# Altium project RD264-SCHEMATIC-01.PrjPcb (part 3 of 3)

## Sheet 6.SchDoc
size 420 x 297 mm
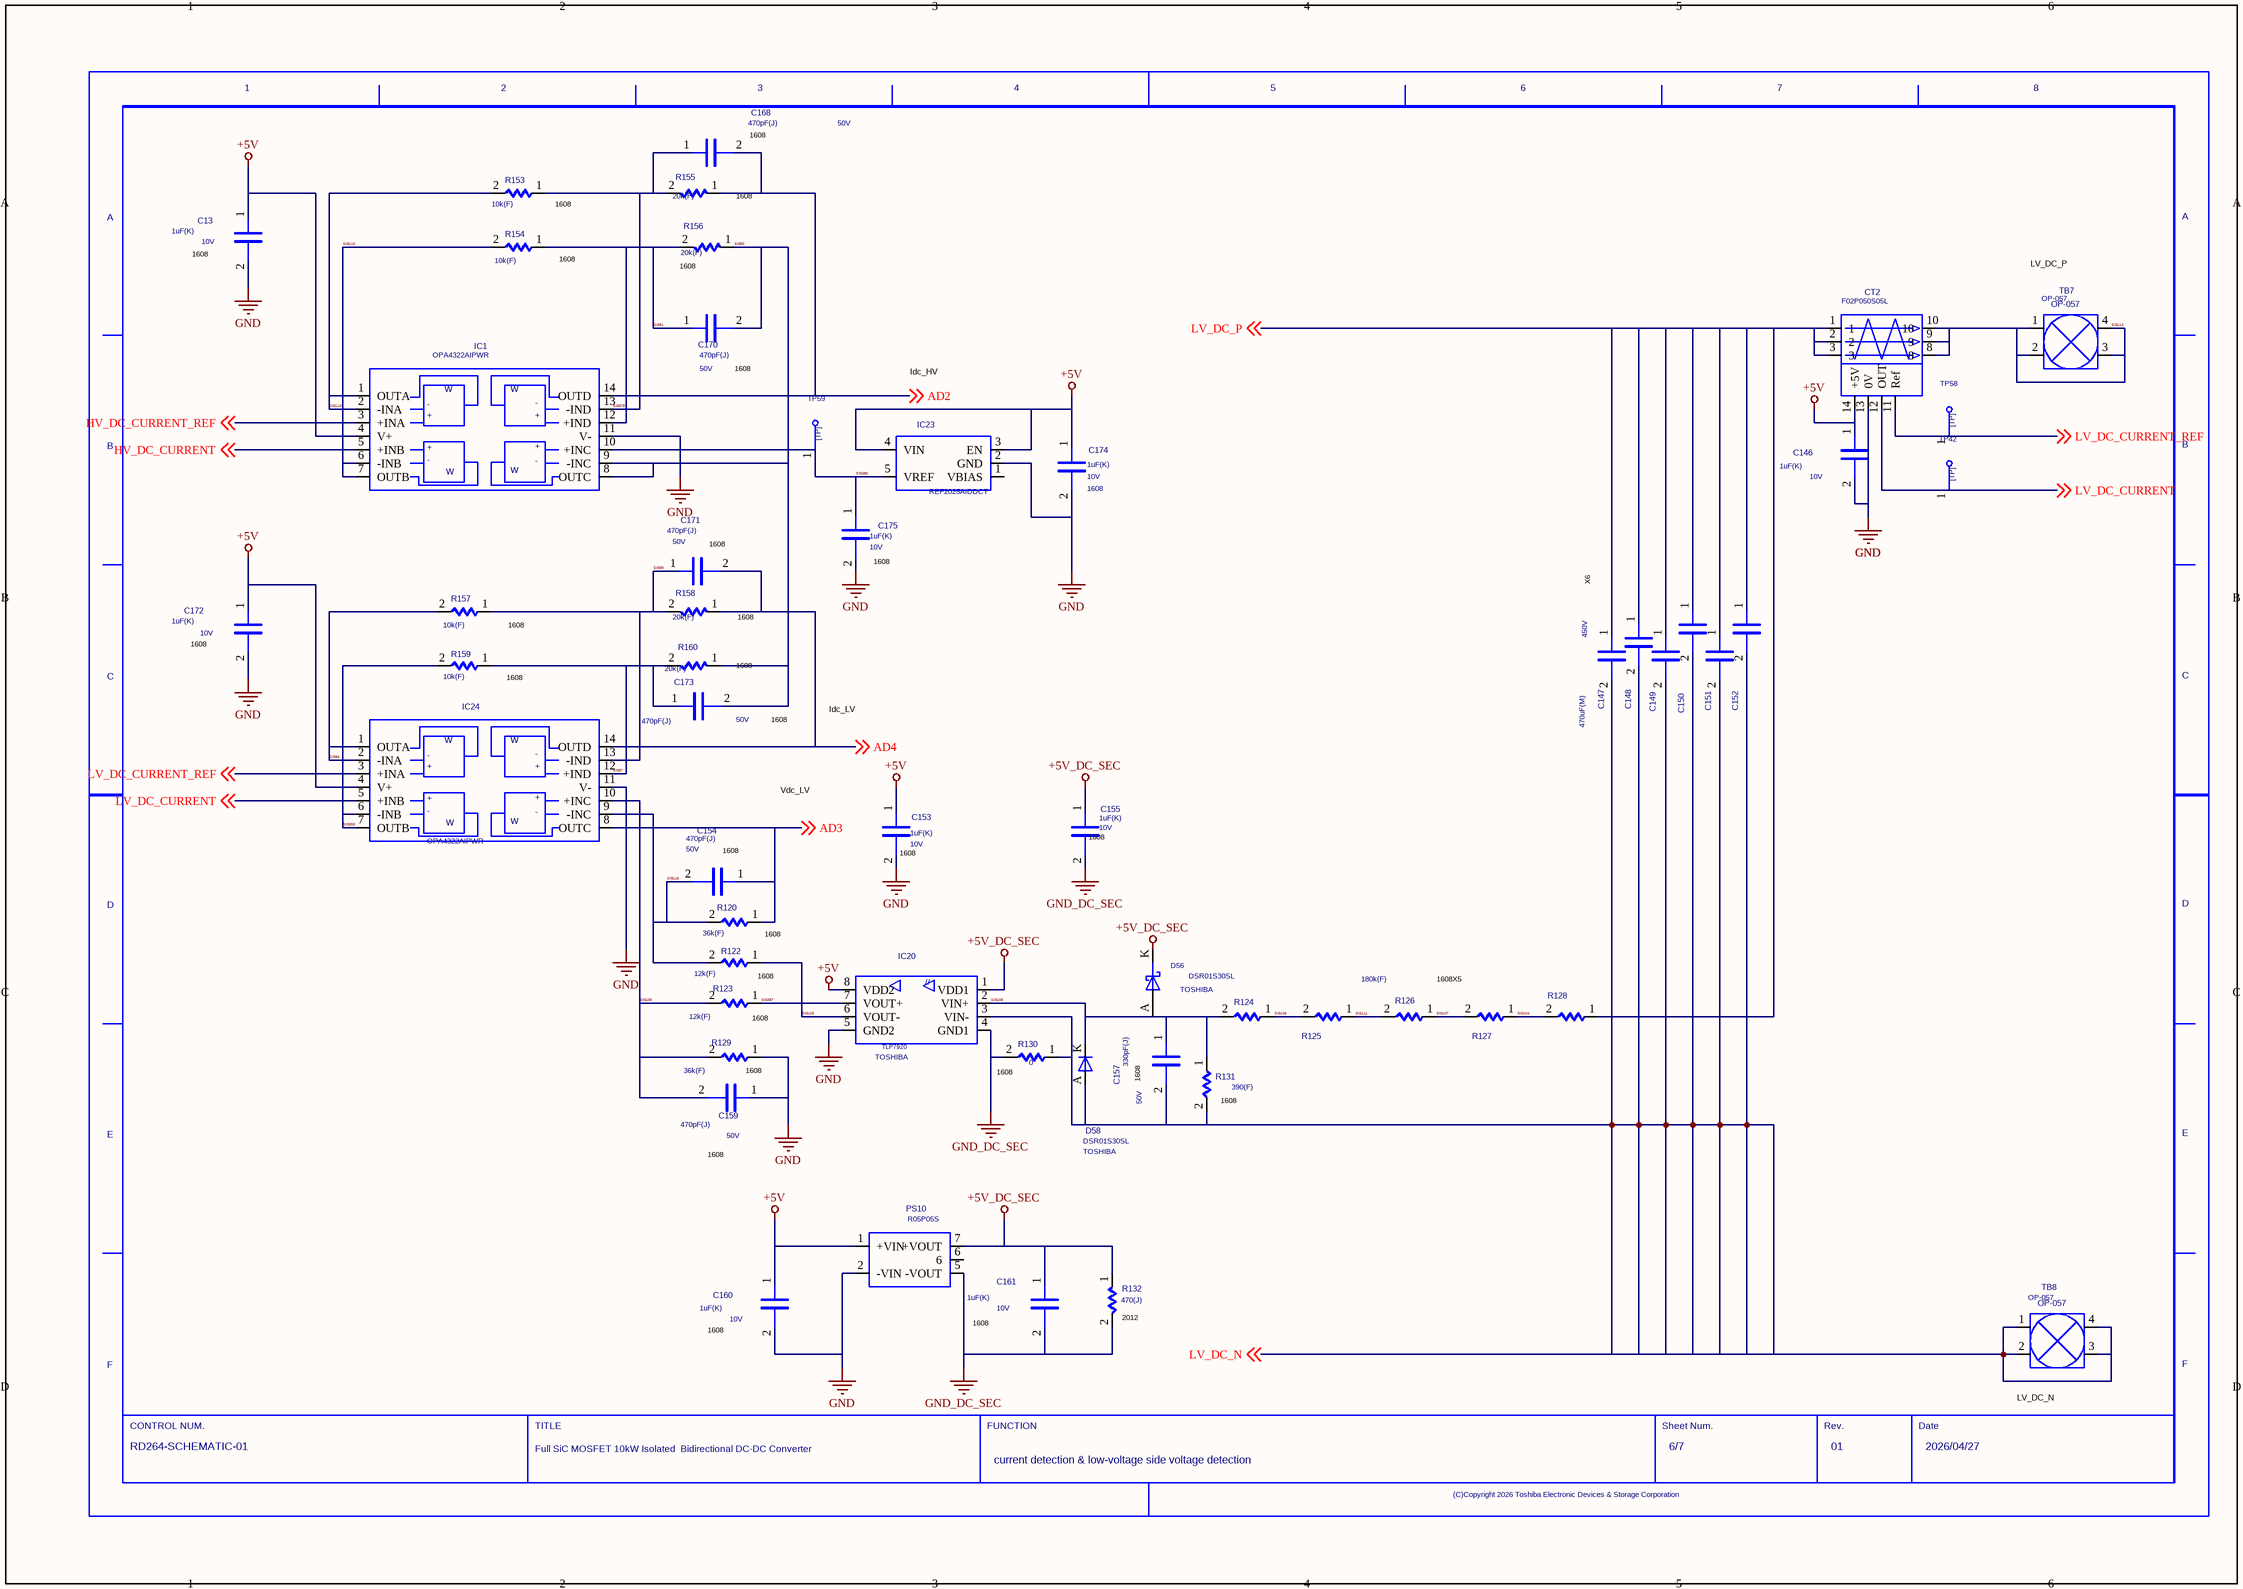
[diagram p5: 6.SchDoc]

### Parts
(Parts that share a designator on the sheet are numbered #1, #2 ... from top to bottom, then left to right.)
C13  VAL1: 1uF(K)  VAL2: 10V  (hidden comment: GRM188R71A105KA61D)
C146  VAL1: 1uF(K)  VAL2: 10V  (hidden comment: GRM188R71A105KA61D)
C147  VAL1: 470uF(M)  VAL2: 450V  (hidden comment: ESMR451VSN471MR40S)
C148  ESMR451VSN471MR40S  (value not drawn)
C149  ESMR451VSN471MR40S  (value not drawn)
C150  ESMR451VSN471MR40S  (value not drawn)
C151  ESMR451VSN471MR40S  (value not drawn)
C152  ESMR451VSN471MR40S  (value not drawn)
C153  VAL2: 10V  VAL1: 1uF(K)  (hidden comment: GRM188R71A105KA61D)
C154  VAL1: 470pF(J)  VAL2: 50V  (hidden comment: GRM1885C1H471JA01D)
C155  VAL1: 1uF(K)  VAL2: 10V  (hidden comment: GRM188R71A105KA61D)
C157  VAL1: 330pF(J)  VAL2: 50V  (hidden comment: GRM1885C1H331JA01D)
C159  VAL1: 470pF(J)  VAL2: 50V  (hidden comment: GRM1885C1H471JA01D)
C160  VAL1: 1uF(K)  VAL2: 10V  (hidden comment: GRM188R71A105KA61D)
C161  VAL1: 1uF(K)  VAL2: 10V  (hidden comment: GRM188R71A105KA61D)
C168  VAL1: 470pF(J)  VAL2: 50V  (hidden comment: GRM1885C1H471JA01D)
C170  VAL1: 470pF(J)  VAL2: 50V  (hidden comment: GRM1885C1H471JA01D)
C171  VAL1: 470pF(J)  VAL2: 50V  (hidden comment: GRM1885C1H471JA01D)
C172  VAL2: 10V  VAL1: 1uF(K)  (hidden comment: GRM188R71A105KA61D)
C173  VAL1: 470pF(J)  VAL2: 50V  (hidden comment: GRM1885C1H471JA01D)
C174  VAL1: 1uF(K)  VAL2: 10V  SIZECODESMD: 1608  (hidden comment: GRM188R71A105KA61D)
C175  VAL1: 1uF(K)  VAL2: 10V  (hidden comment: GRM188R71A105KA61D)
CT2  F02P050S05L
D56  VAL3: DSR01S30SL  USERCOMPTEXT3: TOSHIBA  (hidden comment: SBD)
D58  USERCOMPTEXT3: TOSHIBA  (hidden comment: DSR01S30SL)
IC1  OPA4322AIPWR
IC20  VAL3: TLP7920  USERCOMPTEXT3: TOSHIBA  (hidden comment: TLP7920(LF5,TP5))
IC23  REF2025AIDDCT
IC24  OPA4322AIPWR
PS10  R05P05S
R120  VAL1: 36k(F)  (hidden comment: RK73G1JTTD3602F)
R122  VAL1: 12k(F)  (hidden comment: RK73G1JTTD1202F)
R123  VAL1: 12k(F)  (hidden comment: RK73G1JTTD1202F)
R124  ERJ3EKF1803V  (value not drawn)
R125  ERJ3EKF1803V  (value not drawn)
R126  VAL1: 180k(F)  (hidden comment: ERJ3EKF1803V)
R127  ERJ3EKF1803V  (value not drawn)
R128  ERJ3EKF1803V  (value not drawn)
R129  VAL1: 36k(F)  (hidden comment: RK73G1JTTD3602F)
R130  VAL1: 0  (hidden comment: RK73Z1JTTD)
R131  VAL1: 390(F)  (hidden comment: RK73G1JTTD3900F)
R132  VAL1: 470(J)  (hidden comment: RK73B2ATTD471J)
R153  VAL1: 10k(F)  (hidden comment: RK73H1JTTD1002F)
R154  VAL1: 10k(F)  (hidden comment: RK73H1JTTD1002F)
R155  VAL1: 20k(F)  (hidden comment: RK73H1JTTD2002F)
R156  VAL1: 20k(F)  (hidden comment: RK73H1JTTD2002F)
R157  VAL1: 10k(F)  (hidden comment: RK73H1JTTD1002F)
R158  VAL1: 20k(F)  (hidden comment: RK73H1JTTD2002F)
R159  VAL1: 10k(F)  (hidden comment: RK73H1JTTD1002F)
R160  VAL1: 20k(F)  (hidden comment: RK73H1JTTD2002F)
TB7  OP-057
TB8  OP-057
TP42  TP  (value not drawn)
TP58  TP  (value not drawn)
TP59  TP  (value not drawn)
U?#6  DATE: 2026/04/27  DRAWINGNUMBER: RD264-SCHEMATIC-01  TITLE: Full SiC MOSFET 10kW Isolated / Bidirectional DC-DC Converter  FUNCTION: current detection / & low-voltage side voltage detection  SHEETNUMBER: 6/7  REVISION: 01  (hidden comment: WAKU_DEF100)

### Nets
+5V: C13.1 C146.1 C153.1 C160.1 C172.1 C174.1 CT2.14(+5V) IC1.4(V+) IC20.8(VDD2) IC23.3(EN) IC23.4(VIN) IC24.4(V+) PS10.1(+VIN)
+5V_DC_SEC: C155.1 C161.1 D56.K(C) IC20.1(VDD1) PS10.7(+VOUT) R132.1
GND: C13.2 C146.2 C153.2 C159.1 C160.2 C172.2 C174.2 C175.2 CT2.13(0V) IC1.11(V-) IC20.5(GND2) IC23.2(GND) IC24.11(V-) PS10.2(-VIN) R129.1
GND_DC_SEC: C155.2 C161.2 IC20.4(GND1) PS10.5(-VOUT) R130.2 R132.2
AD2: C168.2 IC1.14(OUTD) R155.1 ; off-sheet AD2
AD3: C154.1 IC24.8(OUTC) R120.1 ; off-sheet AD3
AD4: C171.2 IC24.14(OUTD) R158.1 ; off-sheet AD4
HV_DC_CURRENT: IC1.5(+INB) ; off-sheet HV_DC_CURRENT
HV_DC_CURRENT_REF: IC1.3(+INA) ; off-sheet HV_DC_CURRENT_REF
LV_DC_CURRENT: CT2.12(OUT) IC24.5(+INB) TP42.1 ; off-sheet LV_DC_CURRENT
LV_DC_CURRENT_REF: CT2.11(Ref) IC24.3(+INA) TP58.1 ; off-sheet LV_DC_CURRENT_REF
LV_DC_N: C147.2 C148.2 C149.2 C150.2 C151.2 C152.2 C157.2 D58.A IC20.3(VIN-) R130.1 R131.2 TB8.1 TB8.2 TB8.3 TB8.4 ; off-sheet LV_DC_N
LV_DC_P: C147.1 C148.1 C149.1 C150.1 C151.1 C152.1 CT2.1 CT2.2 CT2.3 R128.1 ; off-sheet LV_DC_P
SIG91: C170.1 IC1.12(+IND) R154.1 R156.2
SIG92: C170.2 C173.2 IC1.8(OUTC) IC1.9(-INC) R156.1 R160.1
SIG94: IC24.1(OUTA) IC24.2(-INA) R157.2
SIG97: C173.1 IC24.12(+IND) R159.1 R160.2
SIG99: C171.1 IC24.13(-IND) R157.1 R158.2
SIG103: IC20.6(VOUT-) R122.1
SIG104: R127.1 R128.2
SIG105: R124.1 R125.2
SIG106: C159.2 IC24.10(+INC) R123.2 R129.2
SIG107: R126.1 R127.2
SIG108: C157.1 D56.A D58.K(C) IC20.2(VIN+) R124.2 R131.1
SIG110: IC1.1(OUTA) IC1.2(-INA) R153.2
SIG111: R125.1 R126.2
SIG113: IC1.6(-INB) IC1.7(OUTB) R154.2
SIG114: CT2.8 CT2.9 CT2.10 TB7.1 TB7.2 TB7.3 TB7.4
SIG115: C154.2 IC24.9(-INC) R120.2 R122.2
SIG378: C168.1 IC1.13(-IND) R153.1 R155.2
SIG380: C175.1 IC1.10(+INC) IC23.5(VREF) TP59.1
SIG387: IC20.7(VOUT+) R123.1
SIG393: IC24.6(-INB) IC24.7(OUTB) R159.2

Not connected (* = marked no-connect by the designer): IC23 1(VBIAS); PS10 6

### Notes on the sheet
- (near C168) 1608
- (near C13) 1608
- (near R153) 1608
- (near R154) 1608
- 1608
- (near R156) 1608
- LV_DC_P
- (near C170) 1608
- Idc_HV
- (near C171) 1608
- (near C175) 1608
- X6
- (near C172) 1608
- (near R159) 1608
- (near C173) 1608
- Idc_LV
- Vdc_LV
- (near C154) 1608
- (near C153) 1608
- (near C155) 1608
- 1608X5
- (near R129) 1608
- (near R123) 1608
- (near R130) 1608
- (near C157) 1608
- (near R131) 1608
- (near C160) 1608
- (near R132) 2012
- (near TB8) LV_DC_N

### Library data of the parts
C13 = C_Dup1: ORIGINALSYMBOLORIGIN: (0,4826); COMP: C-GRM188R71A105KA61D; TIME: 14:31:23; UPDATEUSER: t5459927; SAVECOUNT: 1; INSTANCENAME: INS17335180; REFERENCE TEMPLATE: C; COMPONENTNAME: C_C.Normal_package; NOTE: 1uF 10V
C146 = C_Dup1: ORIGINALSYMBOLORIGIN: (0,4826); COMP: C-GRM188R71A105KA61D; TIME: 14:31:23; UPDATEUSER: t5459927; SAVECOUNT: 1; INSTANCENAME: INS17154372; REFERENCE TEMPLATE: C; COMPONENTNAME: C_C.Normal_package; NOTE: 1uF 10V
C147 = C_Dup1: ORIGINALSYMBOLORIGIN: (0,4826); COMP: C-ESMR451VSN471MR40S; TIME: 14:31:23; UPDATEUSER: t5459927; SAVECOUNT: 1; INSTANCENAME: INS17110408; REFERENCE TEMPLATE: C; COMPONENTNAME: C_C.Normal_package; NOTE: 470uF 450V
C148 = C_Dup1: ORIGINALSYMBOLORIGIN: (0,4826); COMP: C-ESMR451VSN471MR40S; TIME: 14:31:23; UPDATEUSER: t5459927; SAVECOUNT: 1; INSTANCENAME: INS17110416; REFERENCE TEMPLATE: C; COMPONENTNAME: C_C.Normal_package; NOTE: 470uF 450V; VAL1: 470uF(M); VAL2: 450V
C149 = C_Dup1: ORIGINALSYMBOLORIGIN: (0,4826); COMP: C-ESMR451VSN471MR40S; TIME: 14:31:23; UPDATEUSER: t5459927; SAVECOUNT: 1; INSTANCENAME: INS17110424; REFERENCE TEMPLATE: C; COMPONENTNAME: C_C.Normal_package; NOTE: 470uF 450V; VAL1: 470uF(M); VAL2: 450V
C150 = C_Dup1: ORIGINALSYMBOLORIGIN: (0,4826); COMP: C-ESMR451VSN471MR40S; TIME: 14:31:23; UPDATEUSER: t5459927; SAVECOUNT: 1; INSTANCENAME: INS17110469; REFERENCE TEMPLATE: C; COMPONENTNAME: C_C.Normal_package; NOTE: 470uF 450V; VAL1: 470uF(M); VAL2: 450V
C151 = C_Dup1: ORIGINALSYMBOLORIGIN: (0,4826); COMP: C-ESMR451VSN471MR40S; TIME: 14:31:23; UPDATEUSER: t5459927; SAVECOUNT: 1; INSTANCENAME: INS17110477; REFERENCE TEMPLATE: C; COMPONENTNAME: C_C.Normal_package; NOTE: 470uF 450V; VAL1: 470uF(M); VAL2: 450V
C152 = C_Dup1: ORIGINALSYMBOLORIGIN: (0,4826); COMP: C-ESMR451VSN471MR40S; TIME: 14:31:23; UPDATEUSER: t5459927; SAVECOUNT: 1; INSTANCENAME: INS17110485; REFERENCE TEMPLATE: C; COMPONENTNAME: C_C.Normal_package; NOTE: 470uF 450V; VAL1: 470uF(M); VAL2: 450V
C153 = C_Dup1: ORIGINALSYMBOLORIGIN: (0,4826); COMP: C-GRM188R71A105KA61D; TIME: 14:31:23; UPDATEUSER: t5459927; SAVECOUNT: 1; NOTE: 1uF 10V; FUNCN: C_C.Normal_package; REFERENCE TEMPLATE: C; INSTANCENAME: INS17110613
C154 = C_Dup1: ORIGINALSYMBOLORIGIN: (0,4826); COMP: C-GRM1885C1H471JA01D; TIME: 14:31:23; UPDATEUSER: t5459927; SAVECOUNT: 1; INSTANCENAME: INS17110583; REFERENCE TEMPLATE: C; COMPONENTNAME: C_C.Normal_package; NOTE: 470pF 50V
C155 = C_Dup1: ORIGINALSYMBOLORIGIN: (0,4826); COMP: C-GRM188R71A105KA61D; TIME: 14:31:23; UPDATEUSER: t5459927; SAVECOUNT: 1; INSTANCENAME: INS17110613; REFERENCE TEMPLATE: C; COMPONENTNAME: C_C.Normal_package; NOTE: 1uF 10V
C157 = C_Dup1: ORIGINALSYMBOLORIGIN: (0,4826); COMP: C-GRM1885C1H331JA01D; TIME: 14:31:23; UPDATEUSER: t5459927; SAVECOUNT: 1; INSTANCENAME: INS17110887; REFERENCE TEMPLATE: C; COMPONENTNAME: C_C.Normal_package; NOTE: 330pF 50V
C159 = C_Dup1: ORIGINALSYMBOLORIGIN: (0,4826); COMP: C-GRM1885C1H471JA01D; TIME: 14:31:23; UPDATEUSER: t5459927; SAVECOUNT: 1; INSTANCENAME: INS17110939; REFERENCE TEMPLATE: C; COMPONENTNAME: C_C.Normal_package; NOTE: 470pF 50V
C160 = C_Dup1: ORIGINALSYMBOLORIGIN: (0,4826); COMP: C-GRM188R71A105KA61D; TIME: 14:31:23; UPDATEUSER: t5459927; SAVECOUNT: 1; INSTANCENAME: INS17111029; REFERENCE TEMPLATE: C; COMPONENTNAME: C_C.Normal_package; NOTE: 1uF 10V
C161 = C_Dup1: ORIGINALSYMBOLORIGIN: (0,4826); COMP: C-GRM188R71A105KA61D; TIME: 14:31:23; UPDATEUSER: t5459927; SAVECOUNT: 1; INSTANCENAME: INS17111037; REFERENCE TEMPLATE: C; COMPONENTNAME: C_C.Normal_package; NOTE: 1uF 10V
C168 = C_Dup1: ORIGINALSYMBOLORIGIN: (0,4826); COMP: C-GRM1885C1H471JA01D; TIME: 14:31:23; UPDATEUSER: t5459927; SAVECOUNT: 1; INSTANCENAME: INS17330257; REFERENCE TEMPLATE: C; COMPONENTNAME: C_C.Normal_package; NOTE: 470pF 50V
C170 = C_Dup1: ORIGINALSYMBOLORIGIN: (0,4826); COMP: C-GRM1885C1H471JA01D; TIME: 14:31:23; UPDATEUSER: t5459927; SAVECOUNT: 1; INSTANCENAME: INS17330365; REFERENCE TEMPLATE: C; COMPONENTNAME: C_C.Normal_package; NOTE: 470pF 50V
C171 = C_Dup1: ORIGINALSYMBOLORIGIN: (0,4826); COMP: C-GRM1885C1H471JA01D; TIME: 14:31:23; UPDATEUSER: t5459927; SAVECOUNT: 1; INSTANCENAME: INS17330483; REFERENCE TEMPLATE: C; COMPONENTNAME: C_C.Normal_package; NOTE: 470pF 50V
C172 = C_Dup1: ORIGINALSYMBOLORIGIN: (0,4826); COMP: C-GRM188R71A105KA61D; TIME: 14:31:23; UPDATEUSER: t5459927; SAVECOUNT: 1; NOTE: 1uF 10V; FUNCN: C_C.Normal_package; REFERENCE TEMPLATE: C; INSTANCENAME: INS17335180
C173 = C_Dup1: ORIGINALSYMBOLORIGIN: (0,4826); COMP: C-GRM1885C1H471JA01D; TIME: 14:31:23; UPDATEUSER: t5459927; SAVECOUNT: 1; INSTANCENAME: INS17330591; REFERENCE TEMPLATE: C; COMPONENTNAME: C_C.Normal_package; NOTE: 470pF 50V
C174 = C_Dup1: ORIGINALSYMBOLORIGIN: (0,4826); COMP: C-GRM188R71A105KA61D; TIME: 14:31:23; UPDATEUSER: t5459927; SAVECOUNT: 1; INSTANCENAME: INS17336633; REFERENCE TEMPLATE: C; COMPONENTNAME: C_C.Normal_package; NOTE: 1uF 10V
C175 = C_Dup1: ORIGINALSYMBOLORIGIN: (0,4826); COMP: C-GRM188R71A105KA61D; TIME: 14:31:23; UPDATEUSER: t5459927; SAVECOUNT: 1; INSTANCENAME: INS17330751; REFERENCE TEMPLATE: C; COMPONENTNAME: C_C.Normal_package; NOTE: 1uF 10V
CT2 = F02P050S05L: Currnt Transducer; COMP: CT-F02P050S05L; MAKER: Tamura; NOTE: 50At; TIME: 14:31:25; UPDATEUSER: t5459927; UPDATETIME: 14:13:05; SAVECOUNT: 3; SAVEAREA0: -15517,-13418,30208,5711; OriginalSymbolOrigin: (0,0)
D56 = SBD: SAVEAREA0: -4630,-153,17114,13055; TIME: 14:49:55; UPDATEUSER: fukuda-y; UPDATETIME: 08:16:22; SAVECOUNT: 9; OriginalSymbolOrigin: (5080,5080)
D58 = D: PART NUMBER: TMP-433; UPDATEUSER: t5459927; COMP: D-DSR01S30SL; UPDATETIME: 14:31:23; SAVECOUNT: 1; SAVEAREA0: -225,-91,12804,7836; ORIGINALSYMBOLORIGIN: (0,0); INSTANCENAME: INS17313401; FUNCN: D_D.Normal_package; NOTE: 30V 0.1A
IC1 IC24 = OPA4322AIPWR: IC OPAMP; COMP: IC-OPA4322AIPWR; MAKER: Texas Instruments; NOTE: Quad; TIME: 14:31:23; UPDATEUSER: t5459927; UPDATETIME: 14:10:26; SAVECOUNT: 3; SAVEAREA0: -4407,-29582,46539,7769; OriginalSymbolOrigin: (0,0)
IC20 = TLP7920_LF5: Isolation Amplifier; COMP: IC-TLP7920_LF5_TP5; TIME: 14:31:23; UPDATEUSER: t5459927; UPDATETIME: 14:29:27; SAVECOUNT: 3; SAVEAREA0: -27477,-19134,50054,13301; OriginalSymbolOrigin: (0,0)
IC23 = REF2025AIDDCT: 2Voltage References; COMP: IC-REF2025AIDDCT; MAKER: Texas Instruments; TIME: 14:31:24; UPDATEUSER: t5459927; UPDATETIME: 14:11:39; SAVECOUNT: 3; SAVEAREA0: -3467,-13658,20665,4033; OriginalSymbolOrigin: (0,0)
PS10 = R05P05S: DCDC Converter; COMP: PS-R05P05S; MAKER: RECOM; NOTE: 5V in 5V out; TIME: 14:31:25; UPDATEUSER: t5459927; UPDATETIME: 15:35:32; SAVECOUNT: 4; SAVEAREA0: -11227,-12811,26358,2912; OriginalSymbolOrigin: (0,0)
R120 = R: ORIGINALSYMBOLORIGIN: (0,0); COMP: R-RK73G1JTTD3602F; TIME: 14:31:23; UPDATEUSER: t5459927; SAVECOUNT: 1; INSTANCENAME: INS17110637; COMPONENTNAME: R_R.Normal_package; NOTE: 36kohm 0.1W; VAL2: 100mw
R122 = R: ORIGINALSYMBOLORIGIN: (0,0); COMP: R-RK73G1JTTD1202F; TIME: 14:31:23; UPDATEUSER: t5459927; SAVECOUNT: 1; INSTANCENAME: INS17110687; COMPONENTNAME: R_R.Normal_package; NOTE: 12kohm 0.1W; VAL2: 100mw
R123 = R: ORIGINALSYMBOLORIGIN: (0,0); COMP: R-RK73G1JTTD1202F; TIME: 14:31:23; UPDATEUSER: t5459927; SAVECOUNT: 1; INSTANCENAME: INS17110773; COMPONENTNAME: R_R.Normal_package; NOTE: 12kohm 0.1W; VAL2: 100mw
R124 = R: ORIGINALSYMBOLORIGIN: (0,0); COMP: R-ERJ3EKF1803V; TIME: 14:31:23; UPDATEUSER: t5459927; SAVECOUNT: 1; INSTANCENAME: INS17190846; COMPONENTNAME: R_R.Normal_package; NOTE: 180kohm 0.1W; VAL1: 180k(F); VAL2: 100mw
R125 = R: ORIGINALSYMBOLORIGIN: (0,0); COMP: R-ERJ3EKF1803V; TIME: 14:31:23; UPDATEUSER: t5459927; SAVECOUNT: 1; INSTANCENAME: INS17190954; COMPONENTNAME: R_R.Normal_package; NOTE: 180kohm 0.1W; VAL1: 180k(F); VAL2: 100mw
R126 = R: ORIGINALSYMBOLORIGIN: (0,0); COMP: R-ERJ3EKF1803V; TIME: 14:31:23; UPDATEUSER: t5459927; SAVECOUNT: 1; INSTANCENAME: INS17191012; COMPONENTNAME: R_R.Normal_package; NOTE: 180kohm 0.1W; VAL2: 100mw
R127 = R: ORIGINALSYMBOLORIGIN: (0,0); COMP: R-ERJ3EKF1803V; TIME: 14:31:23; UPDATEUSER: t5459927; SAVECOUNT: 1; INSTANCENAME: INS17191162; COMPONENTNAME: R_R.Normal_package; NOTE: 180kohm 0.1W; VAL1: 180k(F); VAL2: 100mw
R128 = R: ORIGINALSYMBOLORIGIN: (0,0); COMP: R-ERJ3EKF1803V; TIME: 14:31:23; UPDATEUSER: t5459927; SAVECOUNT: 1; INSTANCENAME: INS17191255; COMPONENTNAME: R_R.Normal_package; NOTE: 180kohm 0.1W; VAL1: 180k(F); VAL2: 100mw
R129 = R: ORIGINALSYMBOLORIGIN: (0,0); COMP: R-RK73G1JTTD3602F; TIME: 14:31:23; UPDATEUSER: t5459927; SAVECOUNT: 1; INSTANCENAME: INS17110865; COMPONENTNAME: R_R.Normal_package; NOTE: 36kohm 0.1W; VAL2: 100mw
R130 = R: ORIGINALSYMBOLORIGIN: (0,0); COMP: R-RK73Z1JTTD; TIME: 14:31:23; UPDATEUSER: t5459927; SAVECOUNT: 1; INSTANCENAME: INS17110931; COMPONENTNAME: R_R.Normal_package; NOTE: 0ohm 0.1W
R131 = R: ORIGINALSYMBOLORIGIN: (0,0); COMP: R-RK73G1JTTD3900F; TIME: 14:31:23; UPDATEUSER: t5459927; SAVECOUNT: 1; INSTANCENAME: INS17191487; COMPONENTNAME: R_R.Normal_package; NOTE: 390ohm 0.1W; VAL2: 100mw
R132 = R: ORIGINALSYMBOLORIGIN: (0,0); COMP: R-RK73B2ATTD471J; TIME: 14:31:23; UPDATEUSER: t5459927; SAVECOUNT: 1; INSTANCENAME: INS17417097; COMPONENTNAME: R_R.Normal_package; NOTE: 470ohm 0.25W; VAL2: 250mw
R153 = R: ORIGINALSYMBOLORIGIN: (0,0); COMP: R-RK73H1JTTD1002F; TIME: 14:31:23; UPDATEUSER: t5459927; SAVECOUNT: 1; INSTANCENAME: INS17356570; COMPONENTNAME: R_R.Normal_package; NOTE: 10kohm 0.1W; VAL2: 100mw
R154 = R: ORIGINALSYMBOLORIGIN: (0,0); COMP: R-RK73H1JTTD1002F; TIME: 14:31:23; UPDATEUSER: t5459927; SAVECOUNT: 1; INSTANCENAME: INS17356638; COMPONENTNAME: R_R.Normal_package; NOTE: 10kohm 0.1W; VAL2: 100mw
R155 = R: ORIGINALSYMBOLORIGIN: (0,0); COMP: R-RK73H1JTTD2002F; TIME: 14:31:23; UPDATEUSER: t5459927; SAVECOUNT: 1; INSTANCENAME: INS17357275; COMPONENTNAME: R_R.Normal_package; NOTE: 20kohm 0.1W; VAL2: 100mw
R156 = R: ORIGINALSYMBOLORIGIN: (0,0); COMP: R-RK73H1JTTD2002F; TIME: 14:31:23; UPDATEUSER: t5459927; SAVECOUNT: 1; INSTANCENAME: INS17357383; COMPONENTNAME: R_R.Normal_package; NOTE: 20kohm 0.1W; VAL2: 100mw
R157 = R: ORIGINALSYMBOLORIGIN: (0,0); COMP: R-RK73H1JTTD1002F; TIME: 14:31:23; UPDATEUSER: t5459927; SAVECOUNT: 1; INSTANCENAME: INS17356770; COMPONENTNAME: R_R.Normal_package; NOTE: 10kohm 0.1W; VAL2: 100mw
R158 = R: ORIGINALSYMBOLORIGIN: (0,0); COMP: R-RK73H1JTTD2002F; TIME: 14:31:23; UPDATEUSER: t5459927; SAVECOUNT: 1; INSTANCENAME: INS17357470; COMPONENTNAME: R_R.Normal_package; NOTE: 20kohm 0.1W; VAL2: 100mw
R159 = R: ORIGINALSYMBOLORIGIN: (0,0); COMP: R-RK73H1JTTD1002F; TIME: 14:31:23; UPDATEUSER: t5459927; SAVECOUNT: 1; INSTANCENAME: INS17356836; COMPONENTNAME: R_R.Normal_package; NOTE: 10kohm 0.1W; VAL2: 100mw
R160 = R: ORIGINALSYMBOLORIGIN: (0,0); COMP: R-RK73H1JTTD2002F; TIME: 14:31:23; UPDATEUSER: t5459927; SAVECOUNT: 1; INSTANCENAME: INS17357529; COMPONENTNAME: R_R.Normal_package; NOTE: 20kohm 0.1W; VAL2: 100mw
TB7 = OP_057: Terminal Block; PART NUMBER: TMP-784; COMP: TB-OP-057; MAKER: Osada; NOTE: 85A M5; TIME: 14:31:25; UPDATEUSER: t5459927; SAVECOUNT: 1; SAVEAREA0: -3160,-10780,12927,1014; OriginalSymbolOrigin: (0,0); INSTANCENAME: INS17364473; REFERENCE TEMPLATE: TB; COMPONENTNAME: OP-057_OP-057.Normal_package
TB8 = OP_057: Terminal Block; PART NUMBER: TMP-784; COMP: TB-OP-057; MAKER: Osada; NOTE: 85A M5; TIME: 14:31:25; UPDATEUSER: t5459927; SAVECOUNT: 1; SAVEAREA0: -3160,-10780,12927,1014; OriginalSymbolOrigin: (0,0); INSTANCENAME: INS17364565; REFERENCE TEMPLATE: TB; COMPONENTNAME: OP-057_OP-057.Normal_package
TP42 TP58 TP59 = TP: TIME: 16:12:21; UPDATEUSER: fukuda-y; UPDATETIME: 16:18:11; SAVECOUNT: 2; SAVEAREA0: -242,-92,12810,7836; OriginalSymbolOrigin: (0,7620); COMP: TP-HK-3-G; VAL3: HK-3-G
U?#6 = WAKU_DEF100: PLOTTIME: HH:MM; SAVEAREA0: 204655,-40163,430411,63902; TIME: 14:30:25; UPDATEUSER: t5459927; UPDATETIME: 14:22:34; SAVECOUNT: 7; OriginalSymbolOrigin: (10160,284480); SHTSAVECOUNT: 15

## Sheet 7.SchDoc
size 420 x 297 mm
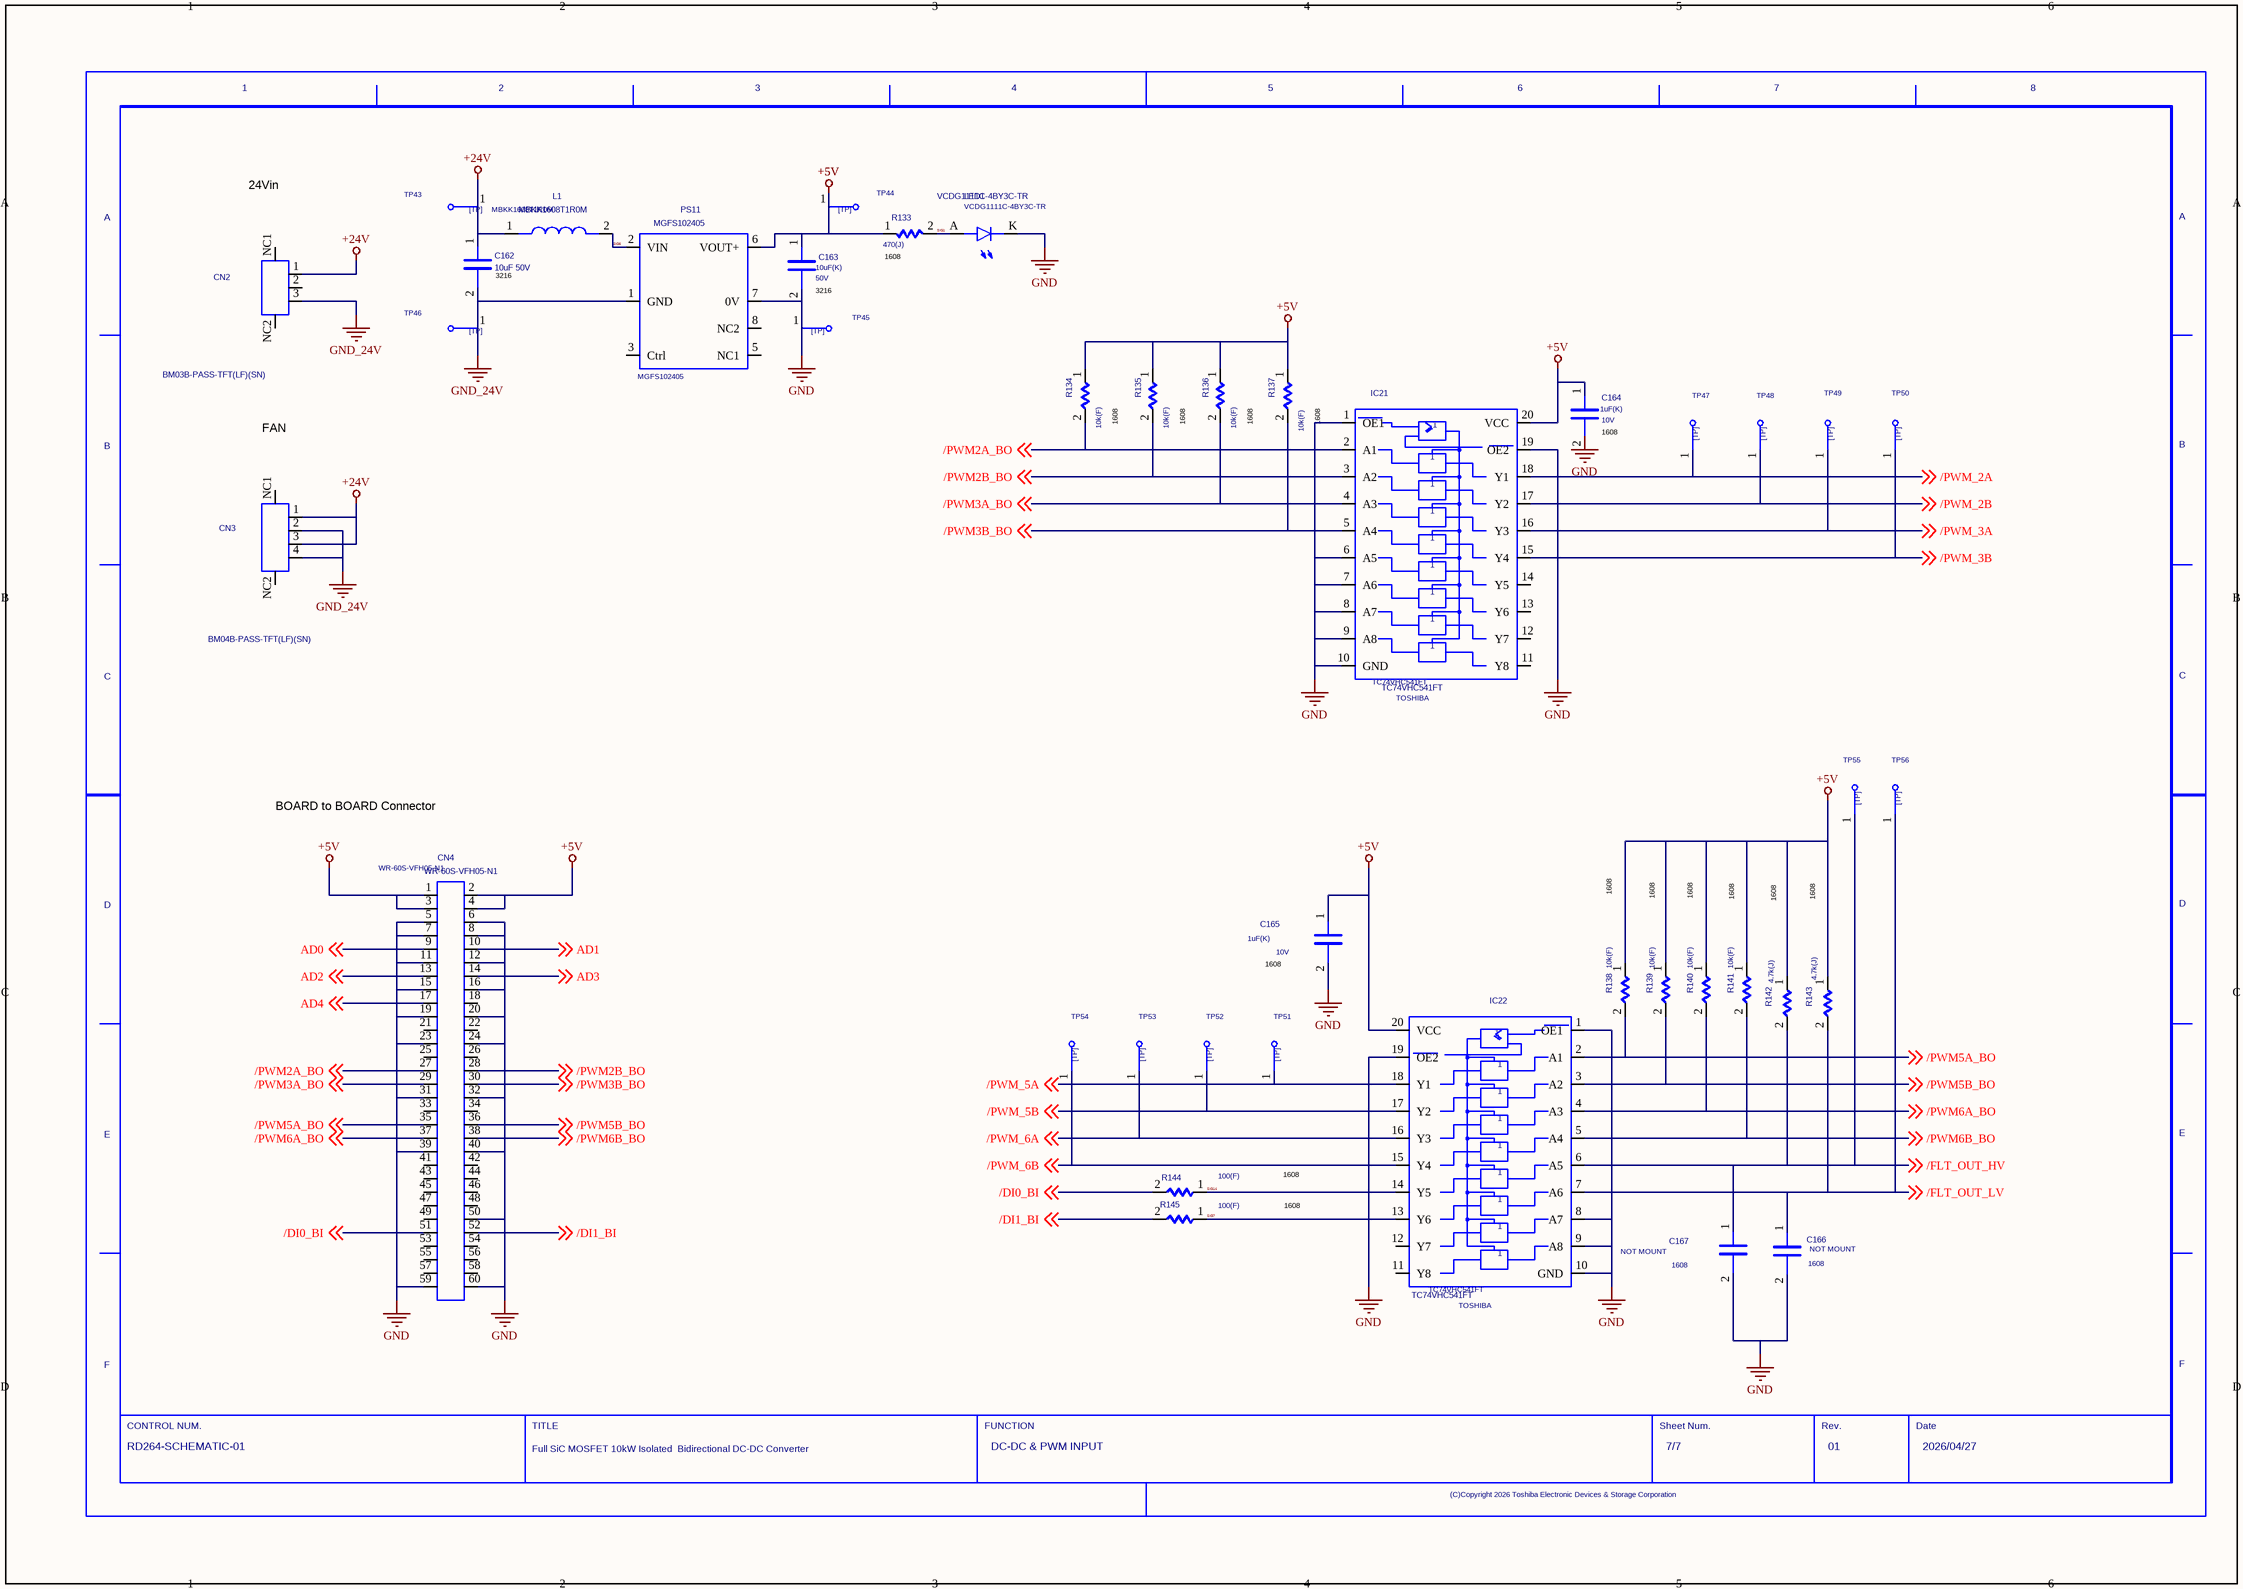
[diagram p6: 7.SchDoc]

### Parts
(Parts that share a designator on the sheet are numbered #1, #2 ... from top to bottom, then left to right.)
C162  NOTE: 10uF 50V  (hidden comment: GRM31CR61H106KA12L)
C163  VAL1: 10uF(K)  VAL2: 50V  (hidden comment: GRM31CR61H106KA12L)
C164  VAL1: 1uF(K)  VAL2: 10V  (hidden comment: GRM188R71A105KA61D)
C165  VAL1: 1uF(K)  VAL2: 10V  (hidden comment: GRM188R71A105KA61D)
C166  NOTMOUNT: NOT MOUNT  SIZECODESMD: 1608  (hidden comment: NC_C1608)
C167  NOTMOUNT: NOT MOUNT  SIZECODESMD: 1608  (hidden comment: NC_C1608)
CN2  BM03B-PASS-TFT(LF)(SN)
CN3  BM04B-PASS-TFT(LF)(SN)
CN4  WR-60S-VFH05-N1
IC21  TC74VHC541FT  USERCOMPTEXT3: TOSHIBA
IC22  TC74VHC541FT  USERCOMPTEXT3: TOSHIBA
L1  MBKK1608T1R0M
LED1  VCDG1111C-4BY3C-TR
PS11  MGFS102405
R133  VAL1: 470(J)  (hidden comment: RK73B1JTTD471J)
R134  VAL1: 10k(F)  (hidden comment: RK73H1JTTD1002F)
R135  VAL1: 10k(F)  (hidden comment: RK73H1JTTD1002F)
R136  VAL1: 10k(F)  (hidden comment: RK73H1JTTD1002F)
R137  VAL1: 10k(F)  (hidden comment: RK73H1JTTD1002F)
R138  VAL1: 10k(F)  (hidden comment: RK73H1JTTD1002F)
R139  VAL1: 10k(F)  (hidden comment: RK73H1JTTD1002F)
R140  VAL1: 10k(F)  (hidden comment: RK73H1JTTD1002F)
R141  VAL1: 10k(F)  (hidden comment: RK73H1JTTD1002F)
R142  VAL1: 4.7k(J)  (hidden comment: RK73B1JTTD472J)
R143  VAL1: 4.7k(J)  (hidden comment: RK73B1JTTD472J)
R144  VAL1: 100(F)  (hidden comment: ERJ3EKF1000V)
R145  VAL1: 100(F)  (hidden comment: ERJ3EKF1000V)
TP43  TP  (value not drawn)
TP44  TP  (value not drawn)
TP45  TP  (value not drawn)
TP46  TP  (value not drawn)
TP47  TP  (value not drawn)
TP48  TP  (value not drawn)
TP49  TP  (value not drawn)
TP50  TP  (value not drawn)
TP51  TP  (value not drawn)
TP52  TP  (value not drawn)
TP53  TP  (value not drawn)
TP54  TP  (value not drawn)
TP55  TP  (value not drawn)
TP56  TP  (value not drawn)
U?#7  DATE: 2026/04/27  DRAWINGNUMBER: RD264-SCHEMATIC-01  TITLE: Full SiC MOSFET 10kW Isolated / Bidirectional DC-DC Converter  FUNCTION: DC-DC & PWM INPUT  SHEETNUMBER: 7/7  REVISION: 01  (hidden comment: WAKU_DEF100)

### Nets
+5V: C163.1 C164.1 C165.1 CN4.1 CN4.2 CN4.3 CN4.4 IC21.20(VCC) IC22.20(VCC) PS11.6(VOUT+) R133.1 R134.1 R135.1 R136.1 R137.1 R138.1 R139.1 R140.1 R141.1 R142.1 R143.1 TP44.1
+24V: C162.1 CN2.1 CN3.1 CN3.3 L1.1 TP43.1
GND: C163.2 C164.2 C165.2 C166.2 C167.2 CN4.5 CN4.6 CN4.7 CN4.8 CN4.11 CN4.12 CN4.15 CN4.16 CN4.19 CN4.20 CN4.23 CN4.24 CN4.31 CN4.32 CN4.39 CN4.40 CN4.50 CN4.59 CN4.60 IC21.1(OE1) IC21.6(A5) IC21.7(A6) IC21.8(A7) IC21.9(A8) IC21.10(GND) IC21.19(OE2) IC22.1(OE1) IC22.8(A7) IC22.9(A8) IC22.10(GND) IC22.19(OE2) LED1.K PS11.7(0V) TP45.1
GND_24V: C162.2 CN2.3 CN3.2 CN3.4 PS11.1(GND) TP46.1
/DI0_BI: CN4.51 R144.2 ; off-sheet /DI0_BI
/DI1_BI: CN4.52 R145.2 ; off-sheet /DI1_BI
/FLT_OUT_HV: C167.1 IC22.6(A5) R142.2 TP55.1 ; off-sheet /FLT_OUT_HV
/FLT_OUT_LV: C166.1 IC22.7(A6) R143.2 TP56.1 ; off-sheet /FLT_OUT_LV
/PWM2A_BO: CN4.27 IC21.2(A1) R134.2 ; off-sheet /PWM2A_BO
/PWM2B_BO: CN4.28 IC21.3(A2) R135.2 ; off-sheet /PWM2B_BO
/PWM3A_BO: CN4.29 IC21.4(A3) R136.2 ; off-sheet /PWM3A_BO
/PWM3B_BO: CN4.30 IC21.5(A4) R137.2 ; off-sheet /PWM3B_BO
/PWM5A_BO: CN4.35 IC22.2(A1) R138.2 ; off-sheet /PWM5A_BO
/PWM5B_BO: CN4.36 IC22.3(A2) R139.2 ; off-sheet /PWM5B_BO
/PWM6A_BO: CN4.37 IC22.4(A3) R140.2 ; off-sheet /PWM6A_BO
/PWM6B_BO: CN4.38 IC22.5(A4) R141.2 ; off-sheet /PWM6B_BO
/PWM_2A: IC21.18(Y1) TP47.1 ; off-sheet /PWM_2A
/PWM_2B: IC21.17(Y2) TP48.1 ; off-sheet /PWM_2B
/PWM_3A: IC21.16(Y3) TP49.1 ; off-sheet /PWM_3A
/PWM_3B: IC21.15(Y4) TP50.1 ; off-sheet /PWM_3B
/PWM_5A: IC22.18(Y1) TP51.1 ; off-sheet /PWM_5A
/PWM_5B: IC22.17(Y2) TP52.1 ; off-sheet /PWM_5B
/PWM_6A: IC22.16(Y3) TP53.1 ; off-sheet /PWM_6A
/PWM_6B: IC22.15(Y4) TP54.1 ; off-sheet /PWM_6B
AD0: CN4.9 ; off-sheet AD0
AD1: CN4.10 ; off-sheet AD1
AD2: CN4.13 ; off-sheet AD2
AD3: CN4.14 ; off-sheet AD3
AD4: CN4.17 ; off-sheet AD4
SIG1: LED1.A R133.2
SIG6: L1.2 PS11.2(VIN)
SIG7: IC22.13(Y6) R145.1
SIG14: IC22.14(Y5) R144.1

Not connected (* = marked no-connect by the designer): CN2 2 NC1(P1) NC2(P2); CN3 NC1(P1) NC2(P2); CN4 18 21 22 25 26 33 34 41 42 43 44 45 46 47 48 49 53 54 55 56 57 58; IC21 11(Y8) 12(Y7) 13(Y6) 14(Y5); IC22 11(Y8) 12(Y7); PS11 3(Ctrl) 5(NC1) 8(NC2)

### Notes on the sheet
- 24Vin
- (near R133) 1608
- (near C162) 3216
- (near C163) 3216
- FAN
- 1608
- (near C164) 1608
- BOARD to BOARD Connector
- (near C165) 1608

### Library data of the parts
C162 = C_Dup1: ORIGINALSYMBOLORIGIN: (0,4826); COMP: C-GRM31CR61H106KA12L; TIME: 14:31:23; UPDATEUSER: t5459927; SAVECOUNT: 1; INSTANCENAME: INS17108792; REFERENCE TEMPLATE: C; COMPONENTNAME: C_C.Normal_package; VAL1: 10uF(K); VAL2: 50V
C163 = C_Dup1: ORIGINALSYMBOLORIGIN: (0,4826); COMP: C-GRM31CR61H106KA12L; TIME: 14:31:23; UPDATEUSER: t5459927; SAVECOUNT: 1; INSTANCENAME: INS17108358; REFERENCE TEMPLATE: C; COMPONENTNAME: C_C.Normal_package; NOTE: 10uF 50V
C164 = C_Dup1: ORIGINALSYMBOLORIGIN: (0,4826); COMP: C-GRM188R71A105KA61D; TIME: 14:31:23; UPDATEUSER: t5459927; SAVECOUNT: 1; INSTANCENAME: INS17108750; REFERENCE TEMPLATE: C; COMPONENTNAME: C_C.Normal_package; NOTE: 1uF 10V
C165 = C_Dup1: ORIGINALSYMBOLORIGIN: (0,4826); COMP: C-GRM188R71A105KA61D; TIME: 14:31:23; UPDATEUSER: t5459927; SAVECOUNT: 1; INSTANCENAME: INS17108480; REFERENCE TEMPLATE: C; COMPONENTNAME: C_C.Normal_package; NOTE: 1uF 10V
C166 = C_Dup1: ORIGINALSYMBOLORIGIN: (0,4826); COMP: C-1608_NM; TIME: 14:31:23; UPDATEUSER: t5459927; SAVECOUNT: 1; INSTANCENAME: INS17108770; REFERENCE TEMPLATE: C; COMPONENTNAME: C_C.Normal_package
C167 = C_Dup1: ORIGINALSYMBOLORIGIN: (0,4826); COMP: C-1608_NM; TIME: 14:31:23; UPDATEUSER: t5459927; SAVECOUNT: 1; INSTANCENAME: INS17108347; REFERENCE TEMPLATE: C; COMPONENTNAME: C_C.Normal_package
CN2 = BM03B_PASS_TFT_LF__SN_: PA Connector; COMP: CN-BM03B-PASS-TFT_LF_SN; MAKER: JST; NOTE: 3pin; TIME: 14:31:24; UPDATEUSER: t5459927; SAVECOUNT: 1; SAVEAREA0: -7641,-13019,14724,3377; OriginalSymbolOrigin: (0,0); INSTANCENAME: INS17108276; REFERENCE TEMPLATE: CN; COMPONENTNAME: BM03B-PASS-TFT(LF)(SN)_BM03B-PASS-TFT(LF)(SN).Normal_package
CN3 = BM04B_PASS_TFT_LF__SN_: PA Connector; COMP: CN-BM04B-PASS-TFT_LF_SN; MAKER: JST; NOTE: 4pin; TIME: 14:31:24; UPDATEUSER: t5459927; SAVECOUNT: 1; SAVEAREA0: -9526,-15610,16566,3519; OriginalSymbolOrigin: (0,0); INSTANCENAME: INS17108649; REFERENCE TEMPLATE: CN; COMPONENTNAME: BM04B-PASS-TFT(LF)(SN)_BM04B-PASS-TFT(LF)(SN).Normal_package
CN4 = WR_60S_VFH05_N1: WR Series; COMP: CN-WR-60S-VFH05-N1; MAKER: JAE; NOTE: 60pin; TIME: 14:31:24; UPDATEUSER: t5459927; SAVECOUNT: 1; SAVEAREA0: -56595,-80318,58967,4405; OriginalSymbolOrigin: (0,0); INSTANCENAME: INS17108513; COMPONENTNAME: WR-60S-VFH05-N1_WR-60S-VFH05-N1.Normal_package
IC21 IC22 = TC74VHC541F: COMP: IC-TC74VHC541FT; TIME: 14:31:23; UPDATEUSER: t5459927; UPDATETIME: 11:00:49; SAVECOUNT: 3; SAVEAREA0: -14417,-48846,43646,-24554; OriginalSymbolOrigin: (0,0)
L1 = MBKK1608T1R0M: Common Mode Filters; COMP: L-MBKK1608T1R0M; MAKER: Taiyo Yuden; TIME: 14:31:24; UPDATEUSER: t5459927; SAVECOUNT: 1; OriginalSymbolOrigin: (0,0); INSTANCENAME: INS17108449; REFERENCE TEMPLATE: L; COMPONENTNAME: MBKK1608T1R0M_MBKK1608T1R0M.Normal_package; NOTE: 1.0uHｱ20% 0.8A
LED1 = VCDG1111C_4BY3C_TR: LED; COMP: LED-VCDG1111C-4BY3C-TR; MAKER: STANLEY; NOTE: Green; TIME: 14:31:24; UPDATEUSER: t5459927; SAVECOUNT: 1; OriginalSymbolOrigin: (0,-2540); INSTANCENAME: INS17108814; COMPONENTNAME: VCDG1111C-4BY3C-TR_VCDG1111C-4BY3C-TR.Normal_package
PS11 = MGFS102405: DCDC Converter; COMP: PS-MGFS102405; MAKER: COSEL; NOTE: 24Vin 5VOut 2A; TIME: 14:31:24; UPDATEUSER: t5459927; SAVECOUNT: 1; SAVEAREA0: -8909,-32686,28368,-5356; OriginalSymbolOrigin: (0,0); INSTANCENAME: INS17108317; COMPONENTNAME: MGFS102405_MGFS102405.Normal_package
R133 = R: ORIGINALSYMBOLORIGIN: (0,0); COMP: R-RK73B1JTTD471J; TIME: 14:31:23; UPDATEUSER: t5459927; SAVECOUNT: 1; INSTANCENAME: INS17266666; COMPONENTNAME: R_R.Normal_package; NOTE: 470ohm 0.1W; VAL2: 125mw
R134 = R: ORIGINALSYMBOLORIGIN: (0,0); COMP: R-RK73H1JTTD1002F; TIME: 14:31:23; UPDATEUSER: t5459927; SAVECOUNT: 1; INSTANCENAME: INS17267993; COMPONENTNAME: R_R.Normal_package; NOTE: 10kohm 0.1W; VAL2: 100mw
R135 = R: ORIGINALSYMBOLORIGIN: (0,0); COMP: R-RK73H1JTTD1002F; TIME: 14:31:23; UPDATEUSER: t5459927; SAVECOUNT: 1; INSTANCENAME: INS17268696; COMPONENTNAME: R_R.Normal_package; NOTE: 10kohm 0.1W; VAL2: 100mw
R136 = R: ORIGINALSYMBOLORIGIN: (0,0); COMP: R-RK73H1JTTD1002F; TIME: 14:31:23; UPDATEUSER: t5459927; SAVECOUNT: 1; INSTANCENAME: INS17268983; COMPONENTNAME: R_R.Normal_package; NOTE: 10kohm 0.1W; VAL2: 100mw
R137 = R: ORIGINALSYMBOLORIGIN: (0,0); COMP: R-RK73H1JTTD1002F; TIME: 14:31:23; UPDATEUSER: t5459927; SAVECOUNT: 1; INSTANCENAME: INS17269149; COMPONENTNAME: R_R.Normal_package; NOTE: 10kohm 0.1W; VAL2: 100mw
R138 = R: ORIGINALSYMBOLORIGIN: (0,0); COMP: R-RK73H1JTTD1002F; TIME: 14:31:23; UPDATEUSER: t5459927; SAVECOUNT: 1; INSTANCENAME: INS17269317; COMPONENTNAME: R_R.Normal_package; NOTE: 10kohm 0.1W; VAL2: 100mw
R139 = R: ORIGINALSYMBOLORIGIN: (0,0); COMP: R-RK73H1JTTD1002F; TIME: 14:31:23; UPDATEUSER: t5459927; SAVECOUNT: 1; INSTANCENAME: INS17269478; COMPONENTNAME: R_R.Normal_package; NOTE: 10kohm 0.1W; VAL2: 100mw
R140 = R: ORIGINALSYMBOLORIGIN: (0,0); COMP: R-RK73H1JTTD1002F; TIME: 14:31:23; UPDATEUSER: t5459927; SAVECOUNT: 1; INSTANCENAME: INS17269639; COMPONENTNAME: R_R.Normal_package; NOTE: 10kohm 0.1W; VAL2: 100mw
R141 = R: ORIGINALSYMBOLORIGIN: (0,0); COMP: R-RK73H1JTTD1002F; TIME: 14:31:23; UPDATEUSER: t5459927; SAVECOUNT: 1; INSTANCENAME: INS17269801; COMPONENTNAME: R_R.Normal_package; NOTE: 10kohm 0.1W; VAL2: 100mw
R142 = R: ORIGINALSYMBOLORIGIN: (0,0); COMP: R-RK73B1JTTD472J; TIME: 14:31:23; UPDATEUSER: t5459927; SAVECOUNT: 1; INSTANCENAME: INS17108297; COMPONENTNAME: R_R.Normal_package; NOTE: 4.7kohm 0.1W; VAL2: 100mw
R143 = R: ORIGINALSYMBOLORIGIN: (0,0); COMP: R-RK73B1JTTD472J; TIME: 14:31:23; UPDATEUSER: t5459927; SAVECOUNT: 1; INSTANCENAME: INS17108672; COMPONENTNAME: R_R.Normal_package; NOTE: 4.7kohm 0.1W; VAL2: 100mw
R144 = R: ORIGINALSYMBOLORIGIN: (0,0); COMP: R-ERJ3EKF1000V; TIME: 14:31:23; UPDATEUSER: t5459927; SAVECOUNT: 1; INSTANCENAME: INS17108491; COMPONENTNAME: R_R.Normal_package; NOTE: 100ohm 0.1W; VAL2: 100mw
R145 = R: ORIGINALSYMBOLORIGIN: (0,0); COMP: R-ERJ3EKF1000V; TIME: 14:31:23; UPDATEUSER: t5459927; SAVECOUNT: 1; INSTANCENAME: INS17108389; COMPONENTNAME: R_R.Normal_package; NOTE: 100ohm 0.1W; VAL2: 100mw
TP43-TP56 = TP: as TP42 on sheet 6
U?#7 = WAKU_DEF100: PLOTTIME: HH:MM; SAVEAREA0: 204655,-40163,430411,63902; TIME: 14:30:25; UPDATEUSER: t5459927; UPDATETIME: 14:24:11; SAVECOUNT: 7; OriginalSymbolOrigin: (10160,284480); SHTSAVECOUNT: 12

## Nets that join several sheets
+5V: 1 (10 pins), 2 (6 pins), 3 (6 pins), 4 (6 pins), 5 (6 pins), 6 (13 pins), 7 (22 pins)
+24V: 2 (C22.1 C42.1 PS2.1 PS3.1), 3 (C54.1 C74.1 PS4.1 PS5.1), 4 (C82.1 C102.1 PS6.1 PS7.1), 5 (C114.1 C134.1 PS8.1 PS9.1), 7 (6 pins)
GND: 1 (13 pins), 2 (6 pins), 3 (6 pins), 4 (6 pins), 5 (6 pins), 6 (15 pins), 7 (39 pins)
GND_24V: 2 (C22.2 C42.2 PS2.2 PS3.2), 3 (C54.2 C74.2 PS4.2 PS5.2), 4 (C82.2 C102.2 PS6.2 PS7.2), 5 (C114.2 C134.2 PS8.2 PS9.2), 7 (6 pins)
/FLT_OUT_HV: 2 (IC4.3 IC6.3), 3 (IC8.3 IC10.3), 7 (C167.1 IC22.6 R142.2 TP55.1)
/FLT_OUT_LV: 4 (IC12.3 IC14.3), 5 (IC16.3 IC18.3), 7 (C166.1 IC22.7 R143.2 TP56.1)
/PWM_2A: 2 (IC4.5 IC4.8 R28.2), 7 (IC21.18 TP47.1)
/PWM_2B: 2 (IC6.5 IC6.8 R40.2), 7 (IC21.17 TP48.1)
/PWM_3A: 3 (IC8.5 IC8.8 R52.2), 7 (IC21.16 TP49.1)
/PWM_3B: 3 (IC10.5 IC10.8 R64.2), 7 (IC21.15 TP50.1)
/PWM_5A: 4 (IC12.5 IC12.8 R75.2), 7 (IC22.18 TP51.1)
/PWM_5B: 4 (IC14.5 IC14.8 R87.2), 7 (IC22.17 TP52.1)
/PWM_6A: 5 (IC16.5 IC16.8 R99.2), 7 (IC22.16 TP53.1)
/PWM_6B: 5 (IC18.5 IC18.8 R111.2), 7 (IC22.15 TP54.1)
AD0: 1 (C15.1 IC19.1 R18.1), 7 (CN4.9)
AD1: 1 (IC19.6 IC19.7), 7 (CN4.10)
AD2: 6 (C168.2 IC1.14 R155.1), 7 (CN4.13)
AD3: 6 (C154.1 IC24.8 R120.1), 7 (CN4.14)
AD4: 6 (C171.2 IC24.14 R158.1), 7 (CN4.17)
HV_DC_CURRENT: 1 (CT1.12 TP1.1), 6 (IC1.5)
HV_DC_CURRENT_REF: 1 (CT1.11 TP57.1), 6 (IC1.3)
HV_DC_N: 1 (13 pins), 2 (20 pins), 3 (20 pins)
HV_DC_P: 1 (8 pins), 2 (7 pins), 3 (7 pins)
LV_DC_N: 4 (20 pins), 5 (20 pins), 6 (15 pins)
LV_DC_P: 4 (7 pins), 5 (7 pins), 6 (10 pins)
